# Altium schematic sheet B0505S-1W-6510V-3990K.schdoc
size 277 x 190 mm; Device: default297x210; Symbol: default297x210; Name: default297x210; Date: 2025.07.04; Rev: V1.1; Size: "A4"; Id: /; File: B0505S-1W-6510V-3990K; Sheet: /; @Page No: 1; @Page Count: 1; @Schematic Name: B0505S-1W-6510V-3990K; @Project Name: 推挽隔离电源-B0505S-1W-6510V-3990K; @Board Name: B0505S-1W-6510V-3990K; @Update Date: 2025-07-04; @Create Time: 17:04:18; @Update Time: 15:07:51; @Page Name: B0505S-1W-6510V-3990K; @Create Date: 2025-06-24
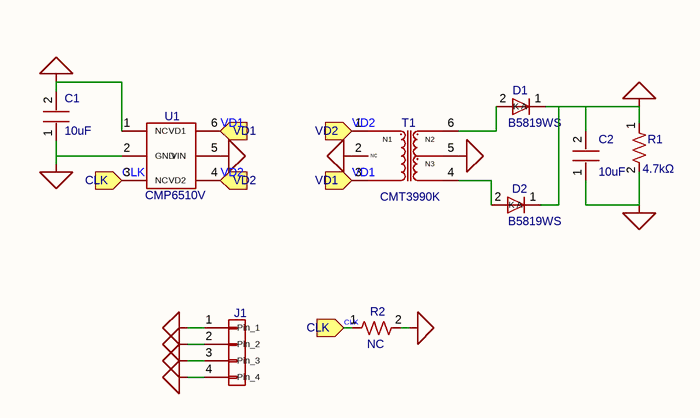
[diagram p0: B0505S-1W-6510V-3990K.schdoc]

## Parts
C1  10uF  [C0603]
C2  10uF  [C0603]
D1  B5819WS  [SOD-323_L1.8-W1.3-LS2.5-RD]
D2  B5819WS  [SOD-323_L1.8-W1.3-LS2.5-RD]
J1  Connector_Generic_Conn_01x04  [coileasy:PinHeader_01x04_P2.54mm_Vertical]  (value not drawn)
R1  4.7kΩ  [R0603]
R2  NC  [R0603]
T1  CMT3990K  [coileasy:CMT38xxx]
U1  CMP6510V  [coileasy:SOT-23-6]

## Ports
CLK (in), VD1 (in), VD2 (in)

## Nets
0V: C2.1 J1.3(Pin_3) R1.2 T1.5
+VO: C2.2 D1.1(K) D2.1(K) J1.4(Pin_4) R1.1
GND: C1.1 J1.1(Pin_1) R2.2 U1.2(GND)
VIN: C1.2 J1.2(Pin_2) T1.2 U1.1(NC) U1.5(VIN)
CLK: R2.1 U1.3(NC) ; port CLK
VD1: T1.3 U1.6(VD1) ; port VD1
VD2: T1.1 U1.4(VD2) ; port VD2
NetD1_2: D1.2(A) T1.6
NetD2_2: D2.2(A) T1.4

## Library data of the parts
C1 C2 = 0603X106K100NT: 容值:10uF;精度:±10%;额定电压:10V;材质(温度系数):X5R;; Manufacturer: FH(风华); Symbol: My_Library_C; AddInBom: yes; ModelId: ac125912035d415993ca9572d50418b1; ModelName: C0603_L1.6-W0.8-H0.8; ModelTransform: 62.992,31.496,0,0,0,0,0,0,0; Tolerance: ±10%; Voltage Rated: 10V; Temperature Coefficient: X5R
D1 D2 = B5819WS_C64886: 二极管配置:独立式;正向压降(Vf):900mV@3A;直流反向耐压(Vr):40V;整流电流:1A;; Manufacturer: MDD(辰达半导体); Symbol: My_Library_D; AddInBom: yes; ModelId: 7459fe65e23146c0a8d836e46a0add72; ModelTransform: 104.3305,51.181,0,0,0,0,0,0,0; Diode Configuration: 独立式; Reverse Voltage (Vr): 40V; Rectified Current: 1A; Reverse Leakage Current (Ir): 1mA@40V
J1 = Connector_Generic_Conn_01x04: Generic connector, single row, 01x04, script generated (kicad-library-utils/schlib/autogen/connector/); Users: REF**; ki_fp_filters: Connector*:*_1x??_*; AddInBom: yes
R1 = RC0603FR-074K7L: 电阻类型:厚膜电阻;阻值:4.7kΩ;精度:±1%;功率:100mW;最大工作电压:75V;温度系数:±100ppm/℃;; Manufacturer: YAGEO(国巨); Symbol: R; AddInBom: yes; ModelId: fc143cca1e79419f9cd78b61e9279f08; ModelTransform: 31.8897,63.7794,0,90,0,0,0,0,0; Tolerance: ±1%; Power(Watts): 100mW; Overload Voltage (Max): 75V
R2 = R: 电阻类型:厚膜电阻;阻值:10kΩ;精度:±1%;功率:100mW;最大工作电压:75V;温度系数:±100ppm/℃;; AddInBom: yes; Tolerance: ±1%; Power(Watts): 100mW; Overload Voltage (Max): 75V; ModelId: fc143cca1e79419f9cd78b61e9279f08
T1 = MYLibrary _CMT38xxxx: Users: REF**; AddInBom: yes
U1 = CMP6510V: CMP6510V 是推挽式变压器驱动器，芯片内部集成一对 N 型功率 MOSFET，通过内部振荡器提供具有精准时序和死区时间的互补驱动信号。驱动器搭配配套的变压器，可以实现输入电压 3.3V/5V, 输出功率不超过 2W 的隔离电源。采用不同的变压器，外围只需搭配简单的二极管，即可获得 3.3V-24V 的非稳压输出。芯片内置软启动、过流保护、过温保护、欠压保护等多种保护功能。; Manufacturer: coileasy(线易); Symbol: MYLibrary_CMP6xxxx; AddInBom: yes; ModelId: 18da8f6c14a34920b3e136b5c401a119; ModelName: SOT-23-6_L2.9-W1.6-H1.5-LS2.8-P0.95; ModelTransform: 110.73671,114.173,0,180,0,0,0.001,-0.003,0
